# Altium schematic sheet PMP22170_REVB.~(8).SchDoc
size 431 x 279 mm; Date: Not shown in title block; ApprovedBy: Not shown in title block; CheckedBy: Not shown in title block; Author: Not shown in title block; CompanyName: Not shown in title block; Engineer: Not shown in title block; Organization: Not shown in title block; Address1: Not shown in title block; Address2: Not shown in title block; Address3: Not shown in title block; Address4: Not shown in title block; DocumentNumber: 1; Revision: Use project parameter SCH_Rev; SheetNumber: 1; SheetTotal: 1; PageSetup: Record=PageOptions¦CenterHorizontal=True¦CenterVertical=True¦PrintScale=1.00¦XCorrection=1.00¦YCorrection=1.00¦PrintKind=0¦BorderSize=5000000¦LeftOffset=0¦BottomOffset=0¦Orientation=2¦PaperLength=1000¦PaperWidth=1000¦Scale=100¦PaperSource=15¦PrintQuality=600¦MediaType=1¦DitherType=10¦PaperKind=Letter¦PrintScaleMode=1
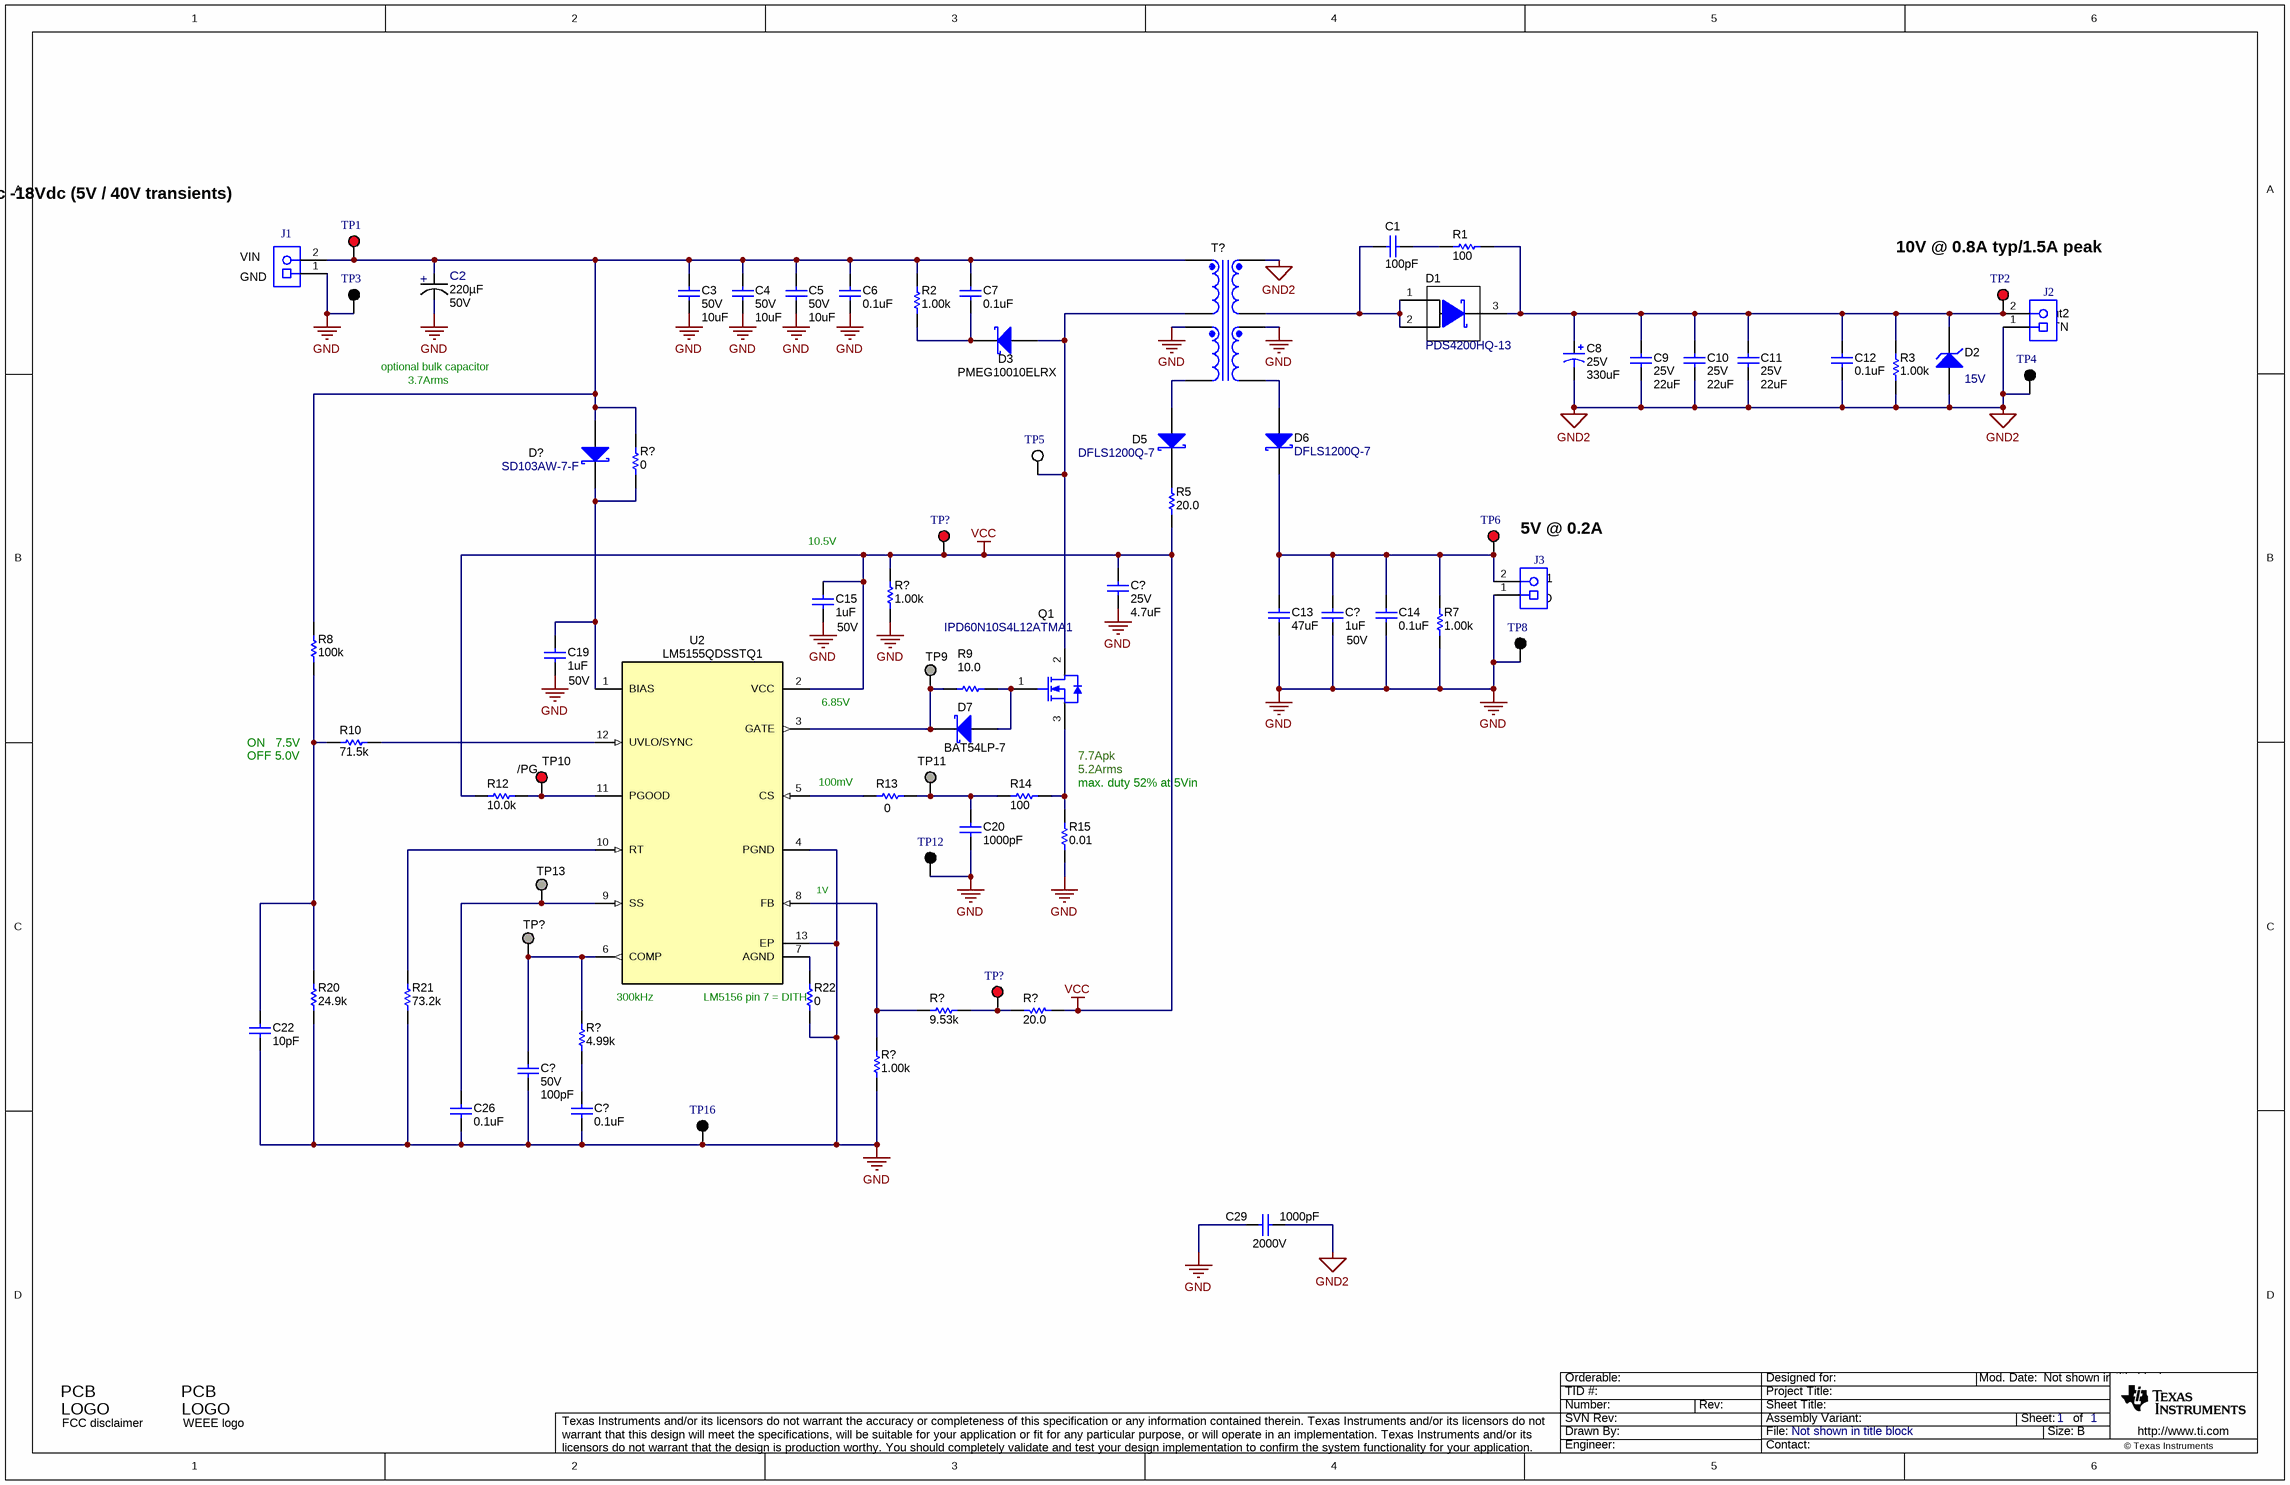
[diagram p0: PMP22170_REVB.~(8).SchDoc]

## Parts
(Parts that share a designator on the sheet are numbered #1, #2 ... from top to bottom, then left to right.)
C1  ValueDisplayed: 100pF  [0805_HV]  (hidden comment: Capacitor)
C2  Cap_F: 220µF  VDC_V: 50V  [FP-EEHZS1H221P_RADIAL_SMD-MFG]  (hidden comment: EEH-ZS1H221V)
C3  VDC_V: 50V  ValueDisplayed: 10uF  [1210_280]  (hidden comment: UMK325AB7106KMHT)
C4  VDC_V: 50V  ValueDisplayed: 10uF  [1210_280]  (hidden comment: UMK325AB7106KMHT)
C5  VDC_V: 50V  ValueDisplayed: 10uF  [1210_280]  (hidden comment: UMK325AB7106KMHT)
C6  ValueDisplayed: 0.1uF  [0603]  (hidden comment: Capacitor)
C7  ValueDisplayed: 0.1uF  [0603]  (hidden comment: Capacitor)
C8  VDC_V: 25V  ValueDisplayed: 330uF  [SM_RADIAL_10BMM]  (hidden comment: EEHZC1E331P)
C9  VDC_V: 25V  ValueDisplayed: 22uF  [1210_270]  (hidden comment: TMK325B7226KMHT)
C10  VDC_V: 25V  ValueDisplayed: 22uF  [1210_270]  (hidden comment: TMK325B7226KMHT)
C11  VDC_V: 25V  ValueDisplayed: 22uF  [1210_270]  (hidden comment: TMK325B7226KMHT)
C12  ValueDisplayed: 0.1uF  [0603]  (hidden comment: Capacitor)
C13  ValueDisplayed: 47uF  [1210_270]  (hidden comment: Capacitor)
C14  ValueDisplayed: 0.1uF  [0603]  (hidden comment: Capacitor)
C15  ValueDisplayed: 1uF  Value2: 50V  [0805_HV1]  (hidden comment: Capacitor)
C19  ValueDisplayed: 1uF  Value2: 50V  [0805_HV1]  (hidden comment: Capacitor)
C20  ValueDisplayed: 1000pF  [0603]  (hidden comment: Capacitor)
C22  ValueDisplayed: 10pF  [0603]  (hidden comment: Capacitor)
C26  ValueDisplayed: 0.1uF  [0603]  (hidden comment: Capacitor)
C29  ValueDisplayed: 1000pF  Value2: 2000V  [1808]  (hidden comment: Capacitor)
C?#1  VDC_V: 25V  ValueDisplayed: 4.7uF  [0805_HV]  (hidden comment: GCM21BC71E475KE36L)
C?#2  ValueDisplayed: 1uF  Value2: 50V  [0805_HV1]  (hidden comment: Capacitor)
C?#3  VDC_V: 50V  ValueDisplayed: 100pF  [0603]  (hidden comment: GCM1885C1H101JA16J)
C?#4  ValueDisplayed: 0.1uF  [0603]  (hidden comment: Capacitor)
D1  PDS4200HQ-13  [POWERDI5]
D2  value 15V  [SOD-123]  (hidden comment: MMSZ5245B-7-F)
D3  PartNumber: PMEG10010ELRX  [SOD-123W]  (hidden comment: DIODE_SCHOTTKY)
D5  DFLS1200Q-7  [PowerDI123]
D6  DFLS1200Q-7  [PowerDI123]
D7  PartNumber: BAT54LP-7  [X1-DFN1006-2]  (hidden comment: DIODE_SCHOTTKY)
D?  SD103AW-7-F  [SOD-123]
J1  Receptacle_2x1  [TERM_BLK_ED555-2DS]  (value not drawn)
J2  Receptacle_2x1  [TERM_BLK_ED555-2DS]  (value not drawn)
J3  Receptacle_2x1  [TERM_BLK_ED555-2DS]  (value not drawn)
Logo1  FCC disclaimer  [FCC_disclaimer]  (no BOM)
Logo2  WEEE logo  [WEEE_Minimum]  (no BOM)
Q1  IPD60N10S4L12ATMA1  [DPAK]
R1  ValueDisplayed: 100  [1206]  (hidden comment: CRCW1206100RFKEAHP)
R2  ValueDisplayed: 1.00k  [1210]  (hidden comment: ERJ14NF1001U)
R3  ValueDisplayed: 1.00k  [1210]  (hidden comment: ERJ14NF1001U)
R5  ValueDisplayed: 20.0  [0805_HV]  (hidden comment: CRCW080520R0FKEA)
R7  ValueDisplayed: 1.00k  [1210]  (hidden comment: ERJ14NF1001U)
R8  ValueDisplayed: 100k  [0603]  (hidden comment: CRCW0603100KFKEA)
R9  ValueDisplayed: 10.0  [0603]  (hidden comment: Resistor)
R10  ValueDisplayed: 71.5k  [0603]  (hidden comment: CRCW060371K5FKEA)
R12  ValueDisplayed: 10.0k  [0603]  (hidden comment: CRCW060310K0FKEA)
R13  ValueDisplayed: 0  [0603]  (hidden comment: Resistor)
R14  ValueDisplayed: 100  [0603]  (hidden comment: Resistor)
R15  ValueDisplayed: 0.01  [0612]  (hidden comment: ERJ-B2CFR01V)
R20  ValueDisplayed: 24.9k  [0603]  (hidden comment: CRCW060324K9FKEA)
R21  ValueDisplayed: 73.2k  [0603]  (hidden comment: CRCW060373K2FKEA)
R22  ValueDisplayed: 0  [0603]  (hidden comment: Resistor)
R?#1  ValueDisplayed: 0  [0603]  (hidden comment: Resistor)
R?#2  ValueDisplayed: 1.00k  [1210]  (hidden comment: ERJ14NF1001U)
R?#3  ValueDisplayed: 9.53k  [0603]  (hidden comment: CRCW06039K53FKEA)
R?#4  ValueDisplayed: 20.0  [0603]  (hidden comment: CRCW060320R0FKEA)
R?#5  ValueDisplayed: 4.99k  [0603]  (hidden comment: CRCW06034K99FKEA)
R?#6  ValueDisplayed: 1.00k  [0603]  (hidden comment: CRCW06031K00FKEA)
T?  7491195331  [WURTH_EPQ13]  (value not drawn)
TP1  5000  [Keystone5000]  (value not drawn)
TP2  5000  [Keystone5000]  (value not drawn)
TP3  5001  [Keystone5001]  (value not drawn)
TP4  5001  [Keystone5001]  (value not drawn)
TP5  5002  [Keystone5002]  (value not drawn)
TP6  5000  [Keystone5000]  (value not drawn)
TP8  5001  [Keystone5001]  (value not drawn)
TP9  TP_SM_1MM  [TP_SM_1MM]  (value not drawn)  (no BOM)
TP10  5000  [Keystone5000]  (value not drawn)
TP11  TP_SM_1MM  [TP_SM_1MM]  (value not drawn)  (no BOM)
TP12  5001  [Keystone5001]  (value not drawn)
TP13  TP_SM_1MM  [TP_SM_1MM]  (value not drawn)  (no BOM)
TP16  5001  [Keystone5001]  (value not drawn)
TP?#1  5000  [Keystone5000]  (value not drawn)
TP?#2  TP_SM_1MM  [TP_SM_1MM]  (value not drawn)  (no BOM)
TP?#3  5000  [Keystone5000]  (value not drawn)
U2  LM5155QDSSTQ1  [DSS0012C]

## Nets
GND: C2.1(CATHODE) C3.2 C4.2 C5.2 C6.2 C13.2 C14.2 C15.2 C19.2 C20.2 C22.2 C26.2 C29.2 C?#1.2 C?#2.2 C?#3.2 C?#4.2 J1.1 J3.1 R7.1 R15.1 R20.1 R21.1 R22.1 R?#2.1 R?#6.1 T?.4 T?.10 TP3.1 TP8.1 TP12.1 TP16.1 U2.4(PGND) U2.13(EP)
GND2: C8.2(-) C9.2 C10.2 C11.2 C12.2 C29.1 D2.2(A) J2.1 R3.1 T?.9 TP4.1
VCC: C15.1 C?#1.1 R5.2 R12.1 R?#2.2 R?#4.2 TP?#1.1 U2.2(VCC)
PG: R12.2 TP10.1 U2.11(PGOOD)
NetC1_1: C1.1 R1.1
NetC1_2: C1.2 D1.1(A) D1.2(A) T?.6
NetC2_2: C2.2(ANODE) C3.1 C4.1 C5.1 C6.1 C7.1 D?.2(A) J1.2 R2.2 R8.2 R?#1.2 T?.1 TP1.1
NetC7_2: C7.2 D3.1(K) R2.1
NetC8_1: C8.1(+) C9.1 C10.1 C11.1 C12.1 D1.3(K) D2.1(K) J2.2 R1.2 R3.2 TP2.1
NetC13_1: C13.1 C14.1 C?#2.1 D6.1(K) J3.2 R7.2 TP6.1
NetC19_1: C19.1 D?.1(K) R?#1.1 U2.1(BIAS)
NetC20_1: C20.1 R13.2 R14.1 TP11.1
NetC22_1: C22.1 R8.1 R10.1 R20.2
NetC26_1: C26.1 TP13.1 U2.9(SS)
NetC?#3_1: C?#3.1 R?#5.2 TP?#2.1 U2.6(COMP)
NetC?#4_1: C?#4.1 R?#5.1
NetD3_2: D3.2(A) Q1.2(D) T?.3 TP5.1
NetD5_1: D5.1(K) R5.1
NetD5_2: D5.2(A) T?.5
NetD6_2: D6.2(A) T?.7
NetD7_1: D7.1(K) R9.2 TP9.1 U2.3(GATE)
NetD7_2: D7.2(A) Q1.1(G) R9.1
NetQ1_3: Q1.3(S) R14.2 R15.2
NetR10_2: R10.2 U2.12(UVLO/SYNC)
NetR13_1: R13.1 U2.5(CS)
NetR21_2: R21.2 U2.10(RT)
NetR22_2: R22.2 U2.7(AGND)
NetR?#3_1: R?#3.1 R?#6.2 U2.8(FB)
NetR?#3_2: R?#3.2 R?#4.1 TP?#3.1

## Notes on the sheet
- Input 6Vdc -18Vdc (5V / 40V transients)
- (near J1) VIN
- (near J1) GND
- 10V @ 0.8A typ/1.5A peak
- optional bulk capacitor
- (near J2) Vout2
- RTN
- 3.7Arms
- 10.5V
- 5V @ 0.2A
- (near J3) Vout1
- (near J3) GND
- (near U2) 6.85V
- (near R10) ON   7.5V
- (near R10) OFF 5.0V
- (near TP10) /PG
- 7.7Apk
- 5.2Arms
- 100mV
- max. duty 52% at 5Vin
- (near U2) 1V
- 300kHz
- (near R22) LM5156 pin 7 = DITH

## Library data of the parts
C1 = CMP-0008236-2: CAP, CERM, 100 pF, 250 V, +/- 5%, C0G/NP0, 0805; PartNumber: GRM21A5C2E101JW01D; Manufacturer: MuRata; Polarized: N; Value: 100pF; U/M: EA; Value1: Unknown; VDC_V: 250V; TaMin_C: -55°C; TaMax_C: 125°C; Cap_Case: 0805; SizeArea_mm2: 2.5; SizeAreaWB_mm2: 6.75; SizeX_mm: 2; SizeY_mm: 1.25; SizeZ_mm: 1.45; AEC Category: Q200
C2 = CMP-0087071-1: 220µF 50V Aluminum Polymer Capacitor Radial, Can - SMD 13 mOhm 4000 Hrs @ 125°C; Manufacturer: Panasonic; SizeZ_mm: 16.8mm; AEC Grade: Grade 1; Symbol Name: SYM-EEHZS1H221P; IRMS_A: 3.7A; Tolerance_%: 20%; AEC Qualified: Yes
C3-C5 = CMP-0009258-2: CAP, CERM, 10 uF, 50 V, +/- 10%, X7R, AEC-Q200 Grade 1, 1210; Manufacturer: Taiyo Yuden; TaMin_C: -55°C; Polarized: N; SizeAreaWB_mm2: 14.7; Value1: Unknown; U/M: EA; Value: 10uF; TaMax_C: 125°C; SizeZ_mm: 2.8; SizeX_mm: 3.2; SizeY_mm: 2.5; Cap_Case: 1210; SizeArea_mm2: 8; AEC Qualified: Y; Cap_F: 10µF; AEC Grade: 1; AEC Category: Q200
C6 C7 C12 = CMP-0007144-4: CAP, CERM, 0.1 uF, 50 V, +/- 10%, X7R, 0603; PartNumber: GCM188R71H104KA57D; Manufacturer: MuRata; Polarized: N; Value: 0.1uF; U/M: EA; Cap_F: 100nF; ESR_ohm: 0.02; Value1: 0.02 ohm; VDC_V: 50V; IRMS_A: 1.84A; TaMin_C: -55°C; TaMax_C: 125°C; AEC Category: Q200; SizeArea_mm2: 1.28; SizeAreaWB_mm2: 4.68; SizeX_mm: 1.6; SizeY_mm: 0.8; SizeZ_mm: 1
C8 = CMP-0012593-3: CAP, Polymer Hybrid, 330 uF, 25 V, +/- 20%, 20 ohm, 10x10 SMD; Manufacturer: Panasonic; TaMin_C: -55°C; ESR_ohm: 20; Polarized: Y; SizeAreaWB_mm2: 159.9; Value1: 20 ohm; Value: 330uF; TaMax_C: 125°C; SizeZ_mm: 10.2; SizeX_mm: 11; SizeY_mm: 10.3; SizeArea_mm2: 113.3; CompType: Capacitor; Cap_F: 330µF; IRMS_A: 2A; AEC Category: Q200
C9-C11 = CMP-0009255-2: CAP, CERM, 22 uF, 25 V, +/- 10%, X7R, AEC-Q200 Grade 1, 1210; Manufacturer: Taiyo Yuden; TaMin_C: -55°C; Polarized: N; SizeAreaWB_mm2: 14.7; Value1: Unknown; U/M: EA; Value: 22uF; TaMax_C: 125°C; SizeZ_mm: 2.7; SizeX_mm: 3.2; SizeY_mm: 2.5; Cap_Case: 1210; SizeArea_mm2: 8; AEC Qualified: Y; Cap_F: 22µF; AEC Grade: 1; AEC Category: Q200
C13 = CMP-0009220-2: CAP, CERM, 47 uF, 10 V, +/- 10%, X7R, 1210; PartNumber: GRM32ER71A476KE15L; Manufacturer: MuRata; Polarized: N; Value: 47uF; U/M: EA; Cap_F: 47µF; Value1: Unknown; VDC_V: 10V; TaMin_C: -55°C; TaMax_C: 125°C; Cap_Case: 1210; SizeArea_mm2: 8; SizeAreaWB_mm2: 14.7; SizeX_mm: 3.2; SizeY_mm: 2.5; SizeZ_mm: 2.7; AEC Category: Q200
C14 C26 C?#4 = CMP-0007378-5: CAP, CERM, 0.1 uF, 16 V, +/- 10%, X7R, 0603; PartNumber: GRM188R71C104KA01D; Manufacturer: MuRata; Polarized: N; Value: 0.1uF; U/M: EA; Cap_F: 100nF; Value1: Unknown; VDC_V: 16V; TaMin_C: -55°C; TaMax_C: 125°C; SizeArea_mm2: 1.28; SizeAreaWB_mm2: 4.68; SizeX_mm: 1.6; SizeY_mm: 0.8; SizeZ_mm: 1; AEC Category: Q200
C15 C19 C?#2 = CMP-0008350-2: CAP, CERM, 1 uF, 50 V, +/- 10%, X7R, 0805; PartNumber: GRM21BR71H105KA12L; Manufacturer: MuRata; Polarized: N; Value: 1uF; U/M: EA; Cap_F: 1µF; Value1: Unknown; TaMin_C: -55°C; TaMax_C: 125°C; Cap_Case: 0805; SizeArea_mm2: 2.5; SizeAreaWB_mm2: 6.75; SizeX_mm: 2; SizeY_mm: 1.25; SizeZ_mm: 1.45; AEC Category: Q200
C20 = CMP-0007402-4: CAP, CERM, 1000 pF, 25 V, +/- 10%, X7R, 0603; PartNumber: GRM188R71E102KA01D; Manufacturer: MuRata; Polarized: N; Value: 1000pF; U/M: EA; Cap_F: 1nF; Value1: Unknown; VDC_V: 25V; TaMin_C: -55°C; TaMax_C: 125°C; SizeArea_mm2: 1.28; SizeAreaWB_mm2: 4.68; SizeX_mm: 1.6; SizeY_mm: 0.8; SizeZ_mm: 1; AEC Category: Q200
C22 = CMP-0007170-4: CAP, CERM, 10 pF, 50 V, +/- 5%, C0G/NP0, 0603; PartNumber: GRM1885C1H100JA01D; Manufacturer: MuRata; Polarized: N; Value: 10pF; U/M: EA; Value1: Unknown; VDC_V: 50V; TaMin_C: -55°C; TaMax_C: 125°C; SizeArea_mm2: 1.28; SizeAreaWB_mm2: 4.68; SizeX_mm: 1.6; SizeY_mm: 0.8; SizeZ_mm: 1; AEC Category: Q200
C29 = CMP-0009436-2: CAP, CERM, 1000 pF, 2000 V, +/- 10%, X7R, 1808; PartNumber: GR442QR73D102KW01L; Manufacturer: MuRata; Polarized: N; Value: 1000pF; U/M: EA; Cap_F: 1nF; Value1: Unknown; VDC_V: 2kV; TaMin_C: -55°C; TaMax_C: 125°C; SizeArea_mm2: 9; SizeAreaWB_mm2: 16.5; SizeX_mm: 4.5; SizeY_mm: 2; SizeZ_mm: 2.03; AEC Category: Q200
C?#1 = CMP-0008013-1: CAP, CERM, 4.7 uF, 25 V, +/- 10%, X7S, AEC-Q200 Grade 1, 0805; Manufacturer: MuRata; TaMin_C: -55°C; Polarized: N; SizeAreaWB_mm2: 6.75; Value1: Unknown; U/M: EA; Value: 4.7uF; TaMax_C: 125°C; SizeZ_mm: 1.45; SizeX_mm: 2; SizeY_mm: 1.25; Cap_Case: 0805; SizeArea_mm2: 2.5; AEC Qualified: Y; Cap_F: 4.7µF; AEC Grade: 1; AEC Category: Q200
C?#3 = CMP-0750041-1: CAP, CERM, 100 pF, 50 V,+/- 5%, C0G/NP0, AEC-Q200 Grade 1, 0603; Manufacturer: MuRata; AEC Grade: 1; SizeArea_mm2: 1.28; SizeX_mm: 1.6; Polarized: N; TaMax_C: 125°C; Value: 100pF; U/M: EA; AEC Qualified: Y; SizeAreaWB_mm2: 4.68; TaMin_C: -55°C; SizeY_mm: 0.8; AEC Category: Q200
D1 = CMP-0081019-2: Diode, Schottky, 200 V, 4 A, AEC-Q101, PowerDI5; Manufacturer: Diodes Inc.; Vf_V: 840mV; Io_A: 4A; SizeX_mm: 6.4; Vr_V: 200V; Value2: 0.84V; AEC Category: Q101; TJmax_C: 175°C; SizeAreaWB_mm2: 49.56; SizeArea_mm2: 24.96; Value: 200V; AEC Qualified: Y; SizeY_mm: 3.9; SizeZ_mm: 1.05
D2 = CMP-0005753-1: Diode, Zener, 15 V, 500 mW, SOD-123; Manufacturer: Diodes Inc.; Power_W: 500mW; SizeAreaWB_mm2: 13.095; Value1: 0.5W; RJA_CperW: 350; U/M: EA; SizeZ_mm: 1.35; SizeX_mm: 3.85; SizeY_mm: 1.7; SizeArea_mm2: 6.545; AEC Category: Q101
D3 = CMP-0028782-2: Diode, Schottky, 100 V, 1 A, AEC-Q101, SOD-123W; Manufacturer: Nexperia; Vf_V: 770mV; Value: 100V; Value1: 1A; Value2: 0.77V; TJmax_C: 175°C; SizeAreaWB_mm2: 12.15; SizeArea_mm2: 5.95; SizeX_mm: 3.5; SizeY_mm: 1.7; SizeZ_mm: 1; AEC Category: Q101; AEC Qualified: Y; Green_Lifecycle: Not Set; Green_REACh: Incomplete
D5 D6 = CMP-0028517-2: Diode, Schottky, 200 V, 1 A, PowerDI123; Manufacturer: Diodes Inc.; Vr_V: 200V; SizeZ_mm: 0.98; Value: 200V; TJmax_C: 175°C; SizeY_mm: 1.78; Vf_V: 850mV; Green_REACh: Passed; Io_A: 1A; Value2: 0.85V; SizeAreaWB_mm2: 13.066; SizeArea_mm2: 6.586; Green_Lifecycle: Active; AEC Category: Q101; SizeX_mm: 3.7; RJC_CperW: 7
D7 = CMP-0076931-2: Diode, Schottky, 30 V, 0.2 A, 1.00x0.50x0.60mm; Manufacturer: Diodes Inc.; Vf_V: 1V; Value: 30V; Value1: 0.2A; Io_A: 200mA; SizeAreaWB_mm2: 3.2; SizeArea_mm2: 0.6; SizeX_mm: 1.0; SizeZ_mm: 0.53; AEC Category: Q101; Green_Lifecycle: Not Set; Green_REACh: Incomplete
D? = CMP-0028543-1: Diode, Schottky, 40 V, 0.35 A, SOD-123; Manufacturer: Diodes Inc.; Io_A: 350mA; Green_Lifecycle: Active; SizeAreaWB_mm2: 13.095; Vr_V: 40V; Green_REACh: Passed; Value1: 0.35A; U/M: EA; Value: 40V; SizeZ_mm: 1.35; SizeX_mm: 3.85; SizeY_mm: 1.7; Vf_V: 550mV; Value2: 0.55V; SizeArea_mm2: 6.545; AEC Category: Q101
J1-J3 = CMP-0074913-1: Terminal Block, 3.5mm Pitch, 2x1, TH; PartNumber: ED555/2DS; Manufacturer: On-Shore Technology; Cert_CULUS: Y; CNHeader: False; ContactFinish: Brass; CT: True; Current_A: 6A; Gender: Female; Green_Lifecycle: Active; Green_REACh: Passed; Pitch_mm: 3.5; Row_Count: 1; Shrouded: N; Voltage_V: 150V
Logo1 = CMP-0074847-1: FCC_disclaimer; Library Reference: Logo
Logo2 = CMP-0074769-1
Q1 = CMP-0080670-2: MOSFET, N-CH, 100 V, 60 A, AEC-Q101, DPAK; Manufacturer: Infineon Technologies; Alternate Manufacturer: None; QgTyp_nC: 38; AEC Category: Q101; Vgs_V: 16V; Value1: 0.015 ohm; SizeAreaWB_mm2: 101.7114; IdsMax_A: 60A; SizeX_mm: 9.91; SizeArea_mm2: 64.8114; Value: 100V; Value2: 38 nC; Rdson45_ohm: 0.015; SizeY_mm: 6.54; ChType: N; AEC Qualified: Y; ChMode: Enhancement; SizeZ_mm: 2.29
R1 = CMP-0016570-3: RES, 100, 1%, 0.5 W, AEC-Q200 Grade 0, 1206; Manufacturer: Vishay-Dale; Power_W: 500mW; TempCo: 100 ppm/C; Value_Code: 100R; Value: 100; EIA_Code: E96; SizeX_mm: 3.2; SizeY_mm: 1.6; SizeZ_mm: 1.35; Value2: 0.5W; SizeArea_mm2: 5.12; AEC Qualified: Y; AEC Grade: 0; AEC Category: Q200
R2 R3 R7 R?#2 = CMP-0015030-3: RES, 1.00 k, 1%, 0.5 W, AEC-Q200 Grade 0, 1210; Manufacturer: Panasonic; Power_W: 500mW; TempCo: 100 ppm/C; SizeAreaWB_mm2: 14.7; Value_Code: 1k00; Value: 1.00k; EIA_Code: E96; Res_ohm: 1k; SizeX_mm: 3.2; SizeY_mm: 2.5; SizeZ_mm: 1.35; Value2: 0.5W; SizeArea_mm2: 8; AEC Qualified: Y; VDC_V: 22V; AEC Category: Q200; AEC Grade: 0
R5 = CMP-0021044-3: RES, 20.0, 1%, 0.125 W, AEC-Q200 Grade 0, 0805; Manufacturer: Vishay-Dale; Power_W: 125mW; Value_Code: 20R0; TempCo: 100 ppm/C; Value: 20.0; EIA_Code: E96; Res_ohm: 20; SizeX_mm: 2; SizeY_mm: 1.25; SizeZ_mm: 1.45; Value2: 0.125W; SizeArea_mm2: 2.5; AEC Qualified: Y; VDC_V: 150V; AEC Category: Q200; AEC Grade: 0
R8 = CMP-0021990-4: RES, 100 k, 1%, 0.1 W, AEC-Q200 Grade 0, 0603; Manufacturer: Vishay-Dale; Power_W: 100mW; TempCo: 100 ppm/C; Value: 100k; EIA_Code: E96; SizeX_mm: 1.6; SizeY_mm: 0.8; SizeZ_mm: 1; Value2: 0.1W; SizeArea_mm2: 1.28; AEC Qualified: Y; VDC_V: 75V; AEC Category: Q200; AEC Grade: 0
R9 = CMP-0022003-4: RES, 10.0, 1%, 0.1 W, AEC-Q200 Grade 0, 0603; PartNumber: CRCW060310R0FKEA; Manufacturer: Vishay-Dale; Value: 10.0; Res_ohm: 10; Value_Code: 10R0; Power_W: 100mW; Value2: 0.1W; VDC_V: 75V; TempCo: 100 ppm/C; SizeArea_mm2: 1.28; SizeX_mm: 1.6; SizeY_mm: 0.8; SizeZ_mm: 1; EIA_Code: E96; AEC Category: Q200; AEC Qualified: Y; AEC Grade: 0
R10 = CMP-0022581-4: RES, 71.5 k, 1%, 0.1 W, AEC-Q200 Grade 0, 0603; Manufacturer: Vishay-Dale; Power_W: 100mW; TempCo: 100 ppm/C; Value_Code: 71k5; Value: 71.5k; EIA_Code: E96; SizeX_mm: 1.6; SizeY_mm: 0.8; SizeZ_mm: 1; Value2: 0.1W; SizeArea_mm2: 1.28; AEC Qualified: Y; VDC_V: 75V; AEC Category: Q200; AEC Grade: 0
R12 = CMP-0021998-4: RES, 10.0 k, 1%, 0.1 W, AEC-Q200 Grade 0, 0603; Manufacturer: Vishay-Dale; Power_W: 100mW; TempCo: 100 ppm/C; Value_Code: 10k0; Value: 10.0k; EIA_Code: E96; Res_ohm: 10k; SizeX_mm: 1.6; SizeY_mm: 0.8; SizeZ_mm: 1; Value2: 0.1W; SizeArea_mm2: 1.28; AEC Qualified: Y; VDC_V: 75V; AEC Category: Q200; AEC Grade: 0
R13 R22 R?#1 = CMP-0025697-4: RES, 0, 5%, 0.1 W, AEC-Q200 Grade 0, 0603; PartNumber: CRCW06030000Z0EA; Manufacturer: Vishay-Dale; Value: 0; Value_Code: 0000; Power_W: 100mW; Value2: 0.1W; VDC_V: 75V; TempCo: 200 ppm/C; SizeArea_mm2: 1.28; SizeX_mm: 1.6; SizeY_mm: 0.8; SizeZ_mm: 1; EIA_Code: E24; AEC Category: Q200; AEC Qualified: Y
R14 = CMP-0021991-4: RES, 100, 1%, 0.1 W, AEC-Q200 Grade 0, 0603; PartNumber: CRCW0603100RFKEA; Manufacturer: Vishay-Dale; Value: 100; Value_Code: 100R; Power_W: 100mW; Value2: 0.1W; VDC_V: 75V; TempCo: 100 ppm/C; SizeArea_mm2: 1.28; SizeX_mm: 1.6; SizeY_mm: 0.8; SizeZ_mm: 1; EIA_Code: E96; AEC Category: Q200; AEC Qualified: Y; AEC Grade: 0
R15 = CMP-0015054-2: RES, 0.01, 1%, 1 W, AEC-Q200 Grade 0, 0612; Manufacturer: Panasonic; Power_W: 1W; TempCo: 300 ppm/C; SizeAreaWB_mm2: 10.92; Value_Code: R010; U/M: EA; Value: 0.01; EIA_Code: E96; SizeX_mm: 1.6; SizeY_mm: 3.2; SizeZ_mm: 0.85; SizeArea_mm2: 5.12; AEC Qualified: Y; AEC Grade: 0; AEC Category: Q200
R20 = CMP-0022237-4: RES, 24.9 k, 1%, 0.1 W, AEC-Q200 Grade 0, 0603; Manufacturer: Vishay-Dale; Power_W: 100mW; TempCo: 100 ppm/C; Value_Code: 24k9; Value: 24.9k; EIA_Code: E96; SizeX_mm: 1.6; SizeY_mm: 0.8; SizeZ_mm: 1; Value2: 0.1W; SizeArea_mm2: 1.28; AEC Qualified: Y; VDC_V: 75V; AEC Category: Q200; AEC Grade: 0
R21 = CMP-0022585-4: RES, 73.2 k, 1%, 0.1 W, AEC-Q200 Grade 0, 0603; Manufacturer: Vishay-Dale; Power_W: 100mW; TempCo: 100 ppm/C; Value_Code: 73k2; Value: 73.2k; EIA_Code: E96; SizeX_mm: 1.6; SizeY_mm: 0.8; SizeZ_mm: 1; Value2: 0.1W; SizeArea_mm2: 1.28; AEC Qualified: Y; VDC_V: 75V; AEC Category: Q200; AEC Grade: 0
R?#3 = CMP-0022667-4: RES, 9.53 k, 1%, 0.1 W, AEC-Q200 Grade 0, 0603; Manufacturer: Vishay-Dale; Power_W: 100mW; TempCo: 100 ppm/C; Value_Code: 9k53; Value: 9.53k; EIA_Code: E96; SizeX_mm: 1.6; SizeY_mm: 0.8; SizeZ_mm: 1; Value2: 0.1W; SizeArea_mm2: 1.28; AEC Qualified: Y; VDC_V: 75V; AEC Category: Q200; AEC Grade: 0
R?#4 = CMP-0022206-4: RES, 20.0, 1%, 0.1 W, AEC-Q200 Grade 0, 0603; Manufacturer: Vishay-Dale; Power_W: 100mW; TempCo: 100 ppm/C; Value_Code: 20R0; Value: 20.0; EIA_Code: E96; Res_ohm: 20; SizeX_mm: 1.6; SizeY_mm: 0.8; SizeZ_mm: 1; Value2: 0.1W; SizeArea_mm2: 1.28; AEC Qualified: Y; VDC_V: 75V; AEC Category: Q200; AEC Grade: 0
R?#5 = CMP-0022458-4: RES, 4.99 k, 1%, 0.1 W, AEC-Q200 Grade 0, 0603; Manufacturer: Vishay-Dale; Power_W: 100mW; TempCo: 100 ppm/C; Value_Code: 4k99; Value: 4.99k; EIA_Code: E96; SizeX_mm: 1.6; SizeY_mm: 0.8; SizeZ_mm: 1; Value2: 0.1W; SizeArea_mm2: 1.28; AEC Qualified: Y; VDC_V: 75V; AEC Category: Q200; AEC Grade: 0
R?#6 = CMP-0022109-5: RES, 1.00 k, 1%, 0.1 W, AEC-Q200 Grade 0, 0603; Manufacturer: Vishay-Dale; Power_W: 100mW; TempCo: 100 ppm/C; Value_Code: 1k00; Value: 1.00k; EIA_Code: E96; Res_ohm: 1k; SizeX_mm: 1.6; SizeY_mm: 0.8; SizeZ_mm: 1; Value2: 0.1W; SizeArea_mm2: 1.28; AEC Qualified: Y; VDC_V: 75V; AEC Category: Q200; AEC Grade: 0
T? = CMP-0030584-1: Transformer, 21 uH, SMT; Manufacturer: Wurth Elektronik; PartNumber: TBD; Rsec2_ohm: 9m; DCR_ohm: 0.032; Rsec3_ohm: 0.145; Ns1toNp: 0.25; Ind_H: 7µH; Ns3toNp: 0.75
TP1 TP2 TP6 TP10 TP?#1 TP?#3 = CMP-0055137-1: Test Point, Miniature, Red, TH; Manufacturer: Keystone; CNHeader: FALSE; ContactFinish: Silver; CT: TRUE; Green_Lifecycle: Active; Green_REACh: Passed
TP3 TP4 TP8 TP12 TP16 = CMP-0055138-1: Test Point, Miniature, Black, TH; Manufacturer: Keystone; CNHeader: FALSE; ContactFinish: Silver; CT: TRUE; Green_Lifecycle: Active; Green_REACh: Passed
TP5 = CMP-0055139-1: Test Point, Miniature, White, TH; Manufacturer: Keystone; ContactFinish: Silver; CNHeader: FALSE; CT: TRUE; Green_Lifecycle: Active; Green_REACh: Passed
TP9 TP11 TP13 TP?#2 = CMP-0003825-1: 1mm Test Point, SMT; Manufacturer: Any
U2 = CMP-0081538-1: Automotive Grade 2.2-MHz Wide Input Non-synchronous Boost Controller, DSS0012C (WSON-12); Alternate PartNumber: LM5155QDSSRQ1; Alternate Manufacturer: Texas Instruments; SizeAreaWB_mm2: 12; SizeZ_mm: 0.8; SizeX_mm: 2; SizeY_mm: 3; SizeArea_mm2: 6; CompType: IC; AEC Qualified: Y; AEC Category: Q200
